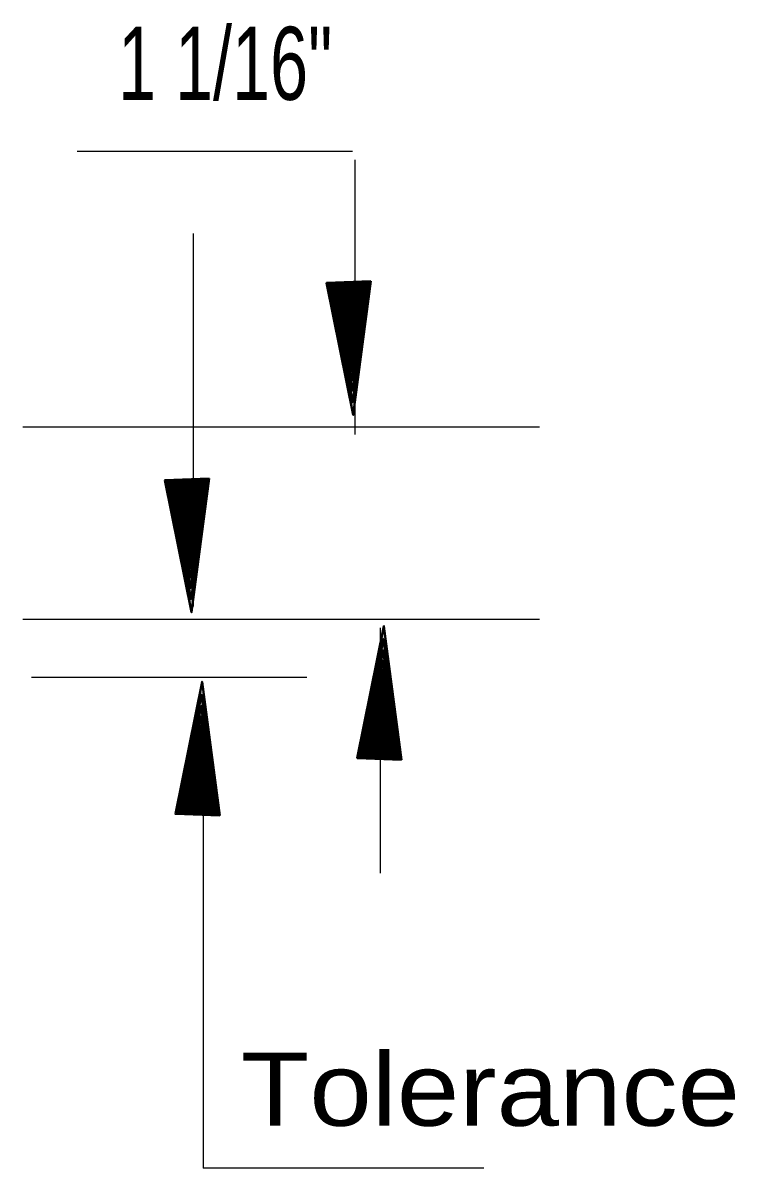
# Model space of a CAD drawing. Extents: x 895.6 to 930.4, y -2278.6 to -2254.7.
# Drawn here: x 907.891 to 909.145, y -2274.318 to -2272.302 of the extents above; entities that cross this region are included whole.
import ezdxf

# ---------------------------------------------------------------- set-up
doc = ezdxf.new("R2010")
doc.units = 0
doc.header["$LTSCALE"] = 0.051
doc.layers.add('1', color=7, linetype='Continuous', lineweight=70)
doc.layers.add('3', color=7, linetype='Continuous', lineweight=40)

msp = doc.modelspace()

# ---------------------------------------------------------------- hatches: boundary and pattern name
at = {"layer": '3'}
for points in [[(908.5035, -2272.75717), (908.4255, -2272.75983), (908.47242, -2272.9925), (908.47242, -2272.9925)], [(908.49958, -2272.75842), (908.42942, -2272.76075), (908.47158, -2272.97008), (908.47158, -2272.97008)], [(908.49608, -2272.75942), (908.433, -2272.76158), (908.471, -2272.95), (908.471, -2272.95)], [(908.493, -2272.76042), (908.43625, -2272.76233), (908.47042, -2272.93192), (908.47042, -2272.93192)], [(908.49033, -2272.76117), (908.43917, -2272.763), (908.46992, -2272.91567), (908.46992, -2272.91567)], [(908.48767, -2272.76217), (908.44167, -2272.76367), (908.46942, -2272.901), (908.46942, -2272.901)], [(908.48533, -2272.76275), (908.44392, -2272.76408), (908.46892, -2272.88783), (908.46892, -2272.88783)], [(908.48342, -2272.7635), (908.44608, -2272.76458), (908.46858, -2272.87583), (908.46858, -2272.87583)], [(908.48158, -2272.76383), (908.44792, -2272.76517), (908.46808, -2272.86525), (908.46808, -2272.86525)], [(908.47983, -2272.7645), (908.4495, -2272.76558), (908.46783, -2272.85558), (908.46783, -2272.85558)], [(908.47833, -2272.765), (908.45117, -2272.76592), (908.4675, -2272.84692), (908.4675, -2272.84692)], [(908.47692, -2272.76533), (908.45258, -2272.76625), (908.46717, -2272.83917), (908.46717, -2272.83917)], [(908.47583, -2272.76583), (908.45375, -2272.7665), (908.467, -2272.832), (908.467, -2272.832)], [(908.47467, -2272.76625), (908.45483, -2272.76675), (908.46683, -2272.82592), (908.46683, -2272.82592)], [(908.47375, -2272.7665), (908.45583, -2272.76708), (908.46667, -2272.82017), (908.46667, -2272.82017)], [(908.47283, -2272.76675), (908.45667, -2272.76717), (908.46633, -2272.81508), (908.46633, -2272.81508)], [(908.472, -2272.767), (908.45742, -2272.7675), (908.46617, -2272.8105), (908.46617, -2272.8105)], [(908.47125, -2272.76717), (908.45825, -2272.76758), (908.46608, -2272.80642), (908.46608, -2272.80642)], [(908.47083, -2272.7675), (908.459, -2272.76775), (908.46608, -2272.80275), (908.46608, -2272.80275)], [(908.47025, -2272.76767), (908.45967, -2272.768), (908.466, -2272.7995), (908.466, -2272.7995)], [(908.46992, -2272.76792), (908.46033, -2272.76825), (908.46617, -2272.7965), (908.46617, -2272.7965)], [(908.46933, -2272.76792), (908.46083, -2272.76825), (908.466, -2272.79375), (908.466, -2272.79375)], [(908.46883, -2272.76808), (908.46125, -2272.76842), (908.46575, -2272.79133), (908.46575, -2272.79133)], [(908.46858, -2272.76825), (908.46175, -2272.7685), (908.46583, -2272.78917), (908.46583, -2272.78917)], [(908.21875, -2273.1045), (908.14075, -2273.10717), (908.18767, -2273.33983), (908.18767, -2273.33983)], [(908.21483, -2273.10575), (908.14467, -2273.10808), (908.18683, -2273.31742), (908.18683, -2273.31742)], [(908.21133, -2273.10675), (908.14825, -2273.10892), (908.18625, -2273.29733), (908.18625, -2273.29733)], [(908.20825, -2273.10775), (908.1515, -2273.10967), (908.18567, -2273.27925), (908.18567, -2273.27925)], [(908.20558, -2273.1085), (908.15442, -2273.11033), (908.18517, -2273.263), (908.18517, -2273.263)], [(908.20292, -2273.1095), (908.15692, -2273.111), (908.18467, -2273.24833), (908.18467, -2273.24833)], [(908.20058, -2273.11008), (908.15917, -2273.11142), (908.18417, -2273.23517), (908.18417, -2273.23517)], [(908.19867, -2273.11083), (908.16133, -2273.11192), (908.18383, -2273.22317), (908.18383, -2273.22317)], [(908.19683, -2273.11117), (908.16317, -2273.1125), (908.18333, -2273.21258), (908.18333, -2273.21258)], [(908.19508, -2273.11183), (908.16475, -2273.11292), (908.18308, -2273.20292), (908.18308, -2273.20292)], [(908.19358, -2273.11233), (908.16642, -2273.11325), (908.18275, -2273.19425), (908.18275, -2273.19425)], [(908.19217, -2273.11267), (908.16783, -2273.11358), (908.18242, -2273.1865), (908.18242, -2273.1865)], [(908.19108, -2273.11317), (908.169, -2273.11383), (908.18225, -2273.17933), (908.18225, -2273.17933)], [(908.18992, -2273.11358), (908.17008, -2273.11408), (908.18208, -2273.17325), (908.18208, -2273.17325)], [(908.189, -2273.11383), (908.17108, -2273.11442), (908.18192, -2273.1675), (908.18192, -2273.1675)], [(908.18808, -2273.11408), (908.17192, -2273.1145), (908.18158, -2273.16242), (908.18158, -2273.16242)], [(908.18725, -2273.11433), (908.17267, -2273.11483), (908.18142, -2273.15783), (908.18142, -2273.15783)], [(908.1865, -2273.1145), (908.1735, -2273.11492), (908.18133, -2273.15375), (908.18133, -2273.15375)], [(908.18608, -2273.11483), (908.17425, -2273.11508), (908.18133, -2273.15008), (908.18133, -2273.15008)], [(908.1855, -2273.115), (908.17492, -2273.11533), (908.18125, -2273.14683), (908.18125, -2273.14683)], [(908.18517, -2273.11525), (908.17558, -2273.11558), (908.18142, -2273.14383), (908.18142, -2273.14383)], [(908.18458, -2273.11525), (908.17608, -2273.11558), (908.18125, -2273.14108), (908.18125, -2273.14108)], [(908.18408, -2273.11542), (908.1765, -2273.11575), (908.181, -2273.13867), (908.181, -2273.13867)], [(908.18383, -2273.11558), (908.177, -2273.11583), (908.18108, -2273.1365), (908.18108, -2273.1365)], [(908.55742, -2273.59975), (908.47942, -2273.59708), (908.52633, -2273.36442), (908.52633, -2273.36442)], [(908.5535, -2273.5985), (908.48333, -2273.59617), (908.5255, -2273.38683), (908.5255, -2273.38683)], [(908.55, -2273.5975), (908.48692, -2273.59533), (908.52492, -2273.40692), (908.52492, -2273.40692)], [(908.54692, -2273.5965), (908.49017, -2273.59458), (908.52433, -2273.425), (908.52433, -2273.425)], [(908.54425, -2273.59575), (908.49308, -2273.59392), (908.52383, -2273.44125), (908.52383, -2273.44125)], [(908.23717, -2273.69767), (908.15917, -2273.695), (908.20608, -2273.46233), (908.20608, -2273.46233)], [(908.54158, -2273.59475), (908.49558, -2273.59325), (908.52333, -2273.45592), (908.52333, -2273.45592)], [(908.53925, -2273.59417), (908.49783, -2273.59283), (908.52283, -2273.46908), (908.52283, -2273.46908)], [(908.23325, -2273.69642), (908.16308, -2273.69408), (908.20525, -2273.48475), (908.20525, -2273.48475)], [(908.53733, -2273.59342), (908.5, -2273.59233), (908.5225, -2273.48108), (908.5225, -2273.48108)], [(908.5355, -2273.59308), (908.50183, -2273.59175), (908.522, -2273.49167), (908.522, -2273.49167)], [(908.22975, -2273.69542), (908.16667, -2273.69325), (908.20467, -2273.50483), (908.20467, -2273.50483)], [(908.53375, -2273.59242), (908.50342, -2273.59133), (908.52175, -2273.50133), (908.52175, -2273.50133)], [(908.53225, -2273.59192), (908.50508, -2273.591), (908.52142, -2273.51), (908.52142, -2273.51)], [(908.22667, -2273.69442), (908.16992, -2273.6925), (908.20408, -2273.52292), (908.20408, -2273.52292)], [(908.53083, -2273.59158), (908.5065, -2273.59067), (908.52108, -2273.51775), (908.52108, -2273.51775)], [(908.52975, -2273.59108), (908.50767, -2273.59042), (908.52092, -2273.52492), (908.52092, -2273.52492)], [(908.52858, -2273.59067), (908.50875, -2273.59017), (908.52075, -2273.531), (908.52075, -2273.531)], [(908.224, -2273.69367), (908.17283, -2273.69183), (908.20358, -2273.53917), (908.20358, -2273.53917)], [(908.52767, -2273.59042), (908.50975, -2273.58983), (908.52058, -2273.53675), (908.52058, -2273.53675)], [(908.52675, -2273.59017), (908.51058, -2273.58975), (908.52025, -2273.54183), (908.52025, -2273.54183)], [(908.52592, -2273.58992), (908.51133, -2273.58942), (908.52008, -2273.54642), (908.52008, -2273.54642)], [(908.52517, -2273.58975), (908.51217, -2273.58933), (908.52, -2273.5505), (908.52, -2273.5505)], [(908.22133, -2273.69267), (908.17533, -2273.69117), (908.20308, -2273.55383), (908.20308, -2273.55383)], [(908.219, -2273.69208), (908.17758, -2273.69075), (908.20258, -2273.567), (908.20258, -2273.567)], [(908.52475, -2273.58942), (908.51292, -2273.58917), (908.52, -2273.55417), (908.52, -2273.55417)], [(908.52417, -2273.58925), (908.51358, -2273.58892), (908.51992, -2273.55742), (908.51992, -2273.55742)], [(908.52383, -2273.589), (908.51425, -2273.58867), (908.52008, -2273.56042), (908.52008, -2273.56042)], [(908.52325, -2273.589), (908.51475, -2273.58867), (908.51992, -2273.56317), (908.51992, -2273.56317)], [(908.52275, -2273.58883), (908.51517, -2273.5885), (908.51967, -2273.56558), (908.51967, -2273.56558)], [(908.5225, -2273.58867), (908.51567, -2273.58842), (908.51975, -2273.56775), (908.51975, -2273.56775)], [(908.21708, -2273.69133), (908.17975, -2273.69025), (908.20225, -2273.579), (908.20225, -2273.579)], [(908.21525, -2273.691), (908.18158, -2273.68967), (908.20175, -2273.58958), (908.20175, -2273.58958)], [(908.2135, -2273.69033), (908.18317, -2273.68925), (908.2015, -2273.59925), (908.2015, -2273.59925)], [(908.212, -2273.68983), (908.18483, -2273.68892), (908.20117, -2273.60792), (908.20117, -2273.60792)], [(908.21058, -2273.6895), (908.18625, -2273.68858), (908.20083, -2273.61567), (908.20083, -2273.61567)], [(908.2095, -2273.689), (908.18742, -2273.68833), (908.20067, -2273.62283), (908.20067, -2273.62283)], [(908.20833, -2273.68858), (908.1885, -2273.68808), (908.2005, -2273.62892), (908.2005, -2273.62892)], [(908.20742, -2273.68833), (908.1895, -2273.68775), (908.20033, -2273.63467), (908.20033, -2273.63467)], [(908.2065, -2273.68808), (908.19033, -2273.68767), (908.2, -2273.63975), (908.2, -2273.63975)], [(908.20567, -2273.68783), (908.19108, -2273.68733), (908.19983, -2273.64433), (908.19983, -2273.64433)], [(908.20492, -2273.68767), (908.19192, -2273.68725), (908.19975, -2273.64842), (908.19975, -2273.64842)], [(908.2045, -2273.68733), (908.19267, -2273.68708), (908.19975, -2273.65208), (908.19975, -2273.65208)], [(908.20392, -2273.68717), (908.19333, -2273.68683), (908.19967, -2273.65533), (908.19967, -2273.65533)], [(908.20358, -2273.68692), (908.194, -2273.68658), (908.19983, -2273.65833), (908.19983, -2273.65833)], [(908.203, -2273.68692), (908.1945, -2273.68658), (908.19967, -2273.66108), (908.19967, -2273.66108)], [(908.2025, -2273.68675), (908.19492, -2273.68642), (908.19942, -2273.6635), (908.19942, -2273.6635)], [(908.20225, -2273.68658), (908.19542, -2273.68633), (908.1995, -2273.66567), (908.1995, -2273.66567)]]:
    msp.add_hatch(color=256, dxfattribs=at).paths.add_polyline_path(points)

# ---------------------------------------------------------------- linework, layer by layer
at = {"layer": '1', "lineweight": 25}
for p, q in [((908.471, -2272.52858), (907.986, -2272.52858)), ((908.47525, -2272.54367), (908.47525, -2273.02692)), ((908.19058, -2272.673), (908.19058, -2273.32967)), ((908.80025, -2273.01408), (907.89058, -2273.01408)), ((908.80025, -2273.3525), (907.89058, -2273.3525)), ((908.51975, -2273.36758), (908.51975, -2273.79925)), ((908.39092, -2273.45467), (907.90592, -2273.45467)), ((908.20833, -2273.49225), (908.20833, -2274.3185)), ((908.70233, -2274.3185), (908.20833, -2274.3185))]:
    msp.add_line(p, q, dxfattribs=at)
at = {"layer": '3'}
for points in [[(908.5035, -2272.75717), (908.4255, -2272.75983), (908.47242, -2272.9925), (908.47242, -2272.9925)], [(908.49958, -2272.75842), (908.42942, -2272.76075), (908.47158, -2272.97008), (908.47158, -2272.97008)], [(908.49608, -2272.75942), (908.433, -2272.76158), (908.471, -2272.95), (908.471, -2272.95)], [(908.493, -2272.76042), (908.43625, -2272.76233), (908.47042, -2272.93192), (908.47042, -2272.93192)], [(908.49033, -2272.76117), (908.43917, -2272.763), (908.46992, -2272.91567), (908.46992, -2272.91567)], [(908.48767, -2272.76217), (908.44167, -2272.76367), (908.46942, -2272.901), (908.46942, -2272.901)], [(908.48533, -2272.76275), (908.44392, -2272.76408), (908.46892, -2272.88783), (908.46892, -2272.88783)], [(908.48342, -2272.7635), (908.44608, -2272.76458), (908.46858, -2272.87583), (908.46858, -2272.87583)], [(908.48158, -2272.76383), (908.44792, -2272.76517), (908.46808, -2272.86525), (908.46808, -2272.86525)], [(908.47983, -2272.7645), (908.4495, -2272.76558), (908.46783, -2272.85558), (908.46783, -2272.85558)], [(908.47833, -2272.765), (908.45117, -2272.76592), (908.4675, -2272.84692), (908.4675, -2272.84692)], [(908.47692, -2272.76533), (908.45258, -2272.76625), (908.46717, -2272.83917), (908.46717, -2272.83917)], [(908.47583, -2272.76583), (908.45375, -2272.7665), (908.467, -2272.832), (908.467, -2272.832)], [(908.47467, -2272.76625), (908.45483, -2272.76675), (908.46683, -2272.82592), (908.46683, -2272.82592)], [(908.47375, -2272.7665), (908.45583, -2272.76708), (908.46667, -2272.82017), (908.46667, -2272.82017)], [(908.47283, -2272.76675), (908.45667, -2272.76717), (908.46633, -2272.81508), (908.46633, -2272.81508)], [(908.472, -2272.767), (908.45742, -2272.7675), (908.46617, -2272.8105), (908.46617, -2272.8105)], [(908.47125, -2272.76717), (908.45825, -2272.76758), (908.46608, -2272.80642), (908.46608, -2272.80642)], [(908.47083, -2272.7675), (908.459, -2272.76775), (908.46608, -2272.80275), (908.46608, -2272.80275)], [(908.47025, -2272.76767), (908.45967, -2272.768), (908.466, -2272.7995), (908.466, -2272.7995)], [(908.46992, -2272.76792), (908.46033, -2272.76825), (908.46617, -2272.7965), (908.46617, -2272.7965)], [(908.46933, -2272.76792), (908.46083, -2272.76825), (908.466, -2272.79375), (908.466, -2272.79375)], [(908.46883, -2272.76808), (908.46125, -2272.76842), (908.46575, -2272.79133), (908.46575, -2272.79133)], [(908.46858, -2272.76825), (908.46175, -2272.7685), (908.46583, -2272.78917), (908.46583, -2272.78917)], [(908.21875, -2273.1045), (908.14075, -2273.10717), (908.18767, -2273.33983), (908.18767, -2273.33983)], [(908.21483, -2273.10575), (908.14467, -2273.10808), (908.18683, -2273.31742), (908.18683, -2273.31742)], [(908.21133, -2273.10675), (908.14825, -2273.10892), (908.18625, -2273.29733), (908.18625, -2273.29733)], [(908.20825, -2273.10775), (908.1515, -2273.10967), (908.18567, -2273.27925), (908.18567, -2273.27925)], [(908.20558, -2273.1085), (908.15442, -2273.11033), (908.18517, -2273.263), (908.18517, -2273.263)], [(908.20292, -2273.1095), (908.15692, -2273.111), (908.18467, -2273.24833), (908.18467, -2273.24833)], [(908.20058, -2273.11008), (908.15917, -2273.11142), (908.18417, -2273.23517), (908.18417, -2273.23517)], [(908.19867, -2273.11083), (908.16133, -2273.11192), (908.18383, -2273.22317), (908.18383, -2273.22317)], [(908.19683, -2273.11117), (908.16317, -2273.1125), (908.18333, -2273.21258), (908.18333, -2273.21258)], [(908.19508, -2273.11183), (908.16475, -2273.11292), (908.18308, -2273.20292), (908.18308, -2273.20292)], [(908.19358, -2273.11233), (908.16642, -2273.11325), (908.18275, -2273.19425), (908.18275, -2273.19425)], [(908.19217, -2273.11267), (908.16783, -2273.11358), (908.18242, -2273.1865), (908.18242, -2273.1865)], [(908.19108, -2273.11317), (908.169, -2273.11383), (908.18225, -2273.17933), (908.18225, -2273.17933)], [(908.18992, -2273.11358), (908.17008, -2273.11408), (908.18208, -2273.17325), (908.18208, -2273.17325)], [(908.189, -2273.11383), (908.17108, -2273.11442), (908.18192, -2273.1675), (908.18192, -2273.1675)], [(908.18808, -2273.11408), (908.17192, -2273.1145), (908.18158, -2273.16242), (908.18158, -2273.16242)], [(908.18725, -2273.11433), (908.17267, -2273.11483), (908.18142, -2273.15783), (908.18142, -2273.15783)], [(908.1865, -2273.1145), (908.1735, -2273.11492), (908.18133, -2273.15375), (908.18133, -2273.15375)], [(908.18608, -2273.11483), (908.17425, -2273.11508), (908.18133, -2273.15008), (908.18133, -2273.15008)], [(908.1855, -2273.115), (908.17492, -2273.11533), (908.18125, -2273.14683), (908.18125, -2273.14683)], [(908.18517, -2273.11525), (908.17558, -2273.11558), (908.18142, -2273.14383), (908.18142, -2273.14383)], [(908.18458, -2273.11525), (908.17608, -2273.11558), (908.18125, -2273.14108), (908.18125, -2273.14108)], [(908.18408, -2273.11542), (908.1765, -2273.11575), (908.181, -2273.13867), (908.181, -2273.13867)], [(908.18383, -2273.11558), (908.177, -2273.11583), (908.18108, -2273.1365), (908.18108, -2273.1365)], [(908.55742, -2273.59975), (908.47942, -2273.59708), (908.52633, -2273.36442), (908.52633, -2273.36442)], [(908.5535, -2273.5985), (908.48333, -2273.59617), (908.5255, -2273.38683), (908.5255, -2273.38683)], [(908.55, -2273.5975), (908.48692, -2273.59533), (908.52492, -2273.40692), (908.52492, -2273.40692)], [(908.54692, -2273.5965), (908.49017, -2273.59458), (908.52433, -2273.425), (908.52433, -2273.425)], [(908.54425, -2273.59575), (908.49308, -2273.59392), (908.52383, -2273.44125), (908.52383, -2273.44125)], [(908.23717, -2273.69767), (908.15917, -2273.695), (908.20608, -2273.46233), (908.20608, -2273.46233)], [(908.54158, -2273.59475), (908.49558, -2273.59325), (908.52333, -2273.45592), (908.52333, -2273.45592)], [(908.53925, -2273.59417), (908.49783, -2273.59283), (908.52283, -2273.46908), (908.52283, -2273.46908)], [(908.23325, -2273.69642), (908.16308, -2273.69408), (908.20525, -2273.48475), (908.20525, -2273.48475)], [(908.53733, -2273.59342), (908.5, -2273.59233), (908.5225, -2273.48108), (908.5225, -2273.48108)], [(908.5355, -2273.59308), (908.50183, -2273.59175), (908.522, -2273.49167), (908.522, -2273.49167)], [(908.22975, -2273.69542), (908.16667, -2273.69325), (908.20467, -2273.50483), (908.20467, -2273.50483)], [(908.53375, -2273.59242), (908.50342, -2273.59133), (908.52175, -2273.50133), (908.52175, -2273.50133)], [(908.53225, -2273.59192), (908.50508, -2273.591), (908.52142, -2273.51), (908.52142, -2273.51)], [(908.22667, -2273.69442), (908.16992, -2273.6925), (908.20408, -2273.52292), (908.20408, -2273.52292)], [(908.53083, -2273.59158), (908.5065, -2273.59067), (908.52108, -2273.51775), (908.52108, -2273.51775)], [(908.52975, -2273.59108), (908.50767, -2273.59042), (908.52092, -2273.52492), (908.52092, -2273.52492)], [(908.52858, -2273.59067), (908.50875, -2273.59017), (908.52075, -2273.531), (908.52075, -2273.531)], [(908.224, -2273.69367), (908.17283, -2273.69183), (908.20358, -2273.53917), (908.20358, -2273.53917)], [(908.52767, -2273.59042), (908.50975, -2273.58983), (908.52058, -2273.53675), (908.52058, -2273.53675)], [(908.52675, -2273.59017), (908.51058, -2273.58975), (908.52025, -2273.54183), (908.52025, -2273.54183)], [(908.52592, -2273.58992), (908.51133, -2273.58942), (908.52008, -2273.54642), (908.52008, -2273.54642)], [(908.52517, -2273.58975), (908.51217, -2273.58933), (908.52, -2273.5505), (908.52, -2273.5505)], [(908.22133, -2273.69267), (908.17533, -2273.69117), (908.20308, -2273.55383), (908.20308, -2273.55383)], [(908.219, -2273.69208), (908.17758, -2273.69075), (908.20258, -2273.567), (908.20258, -2273.567)], [(908.52475, -2273.58942), (908.51292, -2273.58917), (908.52, -2273.55417), (908.52, -2273.55417)], [(908.52417, -2273.58925), (908.51358, -2273.58892), (908.51992, -2273.55742), (908.51992, -2273.55742)], [(908.52383, -2273.589), (908.51425, -2273.58867), (908.52008, -2273.56042), (908.52008, -2273.56042)], [(908.52325, -2273.589), (908.51475, -2273.58867), (908.51992, -2273.56317), (908.51992, -2273.56317)], [(908.52275, -2273.58883), (908.51517, -2273.5885), (908.51967, -2273.56558), (908.51967, -2273.56558)], [(908.5225, -2273.58867), (908.51567, -2273.58842), (908.51975, -2273.56775), (908.51975, -2273.56775)], [(908.21708, -2273.69133), (908.17975, -2273.69025), (908.20225, -2273.579), (908.20225, -2273.579)], [(908.21525, -2273.691), (908.18158, -2273.68967), (908.20175, -2273.58958), (908.20175, -2273.58958)], [(908.2135, -2273.69033), (908.18317, -2273.68925), (908.2015, -2273.59925), (908.2015, -2273.59925)], [(908.212, -2273.68983), (908.18483, -2273.68892), (908.20117, -2273.60792), (908.20117, -2273.60792)], [(908.21058, -2273.6895), (908.18625, -2273.68858), (908.20083, -2273.61567), (908.20083, -2273.61567)], [(908.2095, -2273.689), (908.18742, -2273.68833), (908.20067, -2273.62283), (908.20067, -2273.62283)], [(908.20833, -2273.68858), (908.1885, -2273.68808), (908.2005, -2273.62892), (908.2005, -2273.62892)], [(908.20742, -2273.68833), (908.1895, -2273.68775), (908.20033, -2273.63467), (908.20033, -2273.63467)], [(908.2065, -2273.68808), (908.19033, -2273.68767), (908.2, -2273.63975), (908.2, -2273.63975)], [(908.20567, -2273.68783), (908.19108, -2273.68733), (908.19983, -2273.64433), (908.19983, -2273.64433)], [(908.20492, -2273.68767), (908.19192, -2273.68725), (908.19975, -2273.64842), (908.19975, -2273.64842)], [(908.2045, -2273.68733), (908.19267, -2273.68708), (908.19975, -2273.65208), (908.19975, -2273.65208)], [(908.20392, -2273.68717), (908.19333, -2273.68683), (908.19967, -2273.65533), (908.19967, -2273.65533)], [(908.20358, -2273.68692), (908.194, -2273.68658), (908.19983, -2273.65833), (908.19983, -2273.65833)], [(908.203, -2273.68692), (908.1945, -2273.68658), (908.19967, -2273.66108), (908.19967, -2273.66108)], [(908.2025, -2273.68675), (908.19492, -2273.68642), (908.19942, -2273.6635), (908.19942, -2273.6635)], [(908.20225, -2273.68658), (908.19542, -2273.68633), (908.1995, -2273.66567), (908.1995, -2273.66567)]]:
    msp.add_lwpolyline(points, close=True, dxfattribs=at)

# ---------------------------------------------------------------- texts
at = {"layer": '1'}
for s, width, p in [('1 1/16"', 0.7, (908.05817, -2272.43783)), ('Tolerance', 1.15, (908.27442, -2274.244))]:
    msp.add_text(s, height=0.1286, dxfattribs=dict(at, width=width)).set_placement(p)

doc.saveas('drawing.dxf')
